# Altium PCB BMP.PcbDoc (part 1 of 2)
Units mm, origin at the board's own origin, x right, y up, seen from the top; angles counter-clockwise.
Board outline 171.87 x 76.56 mm, 2 copper layers (Top Layer, Bottom Layer); 88 components, 25 nets, 514 pads, 181 vias.
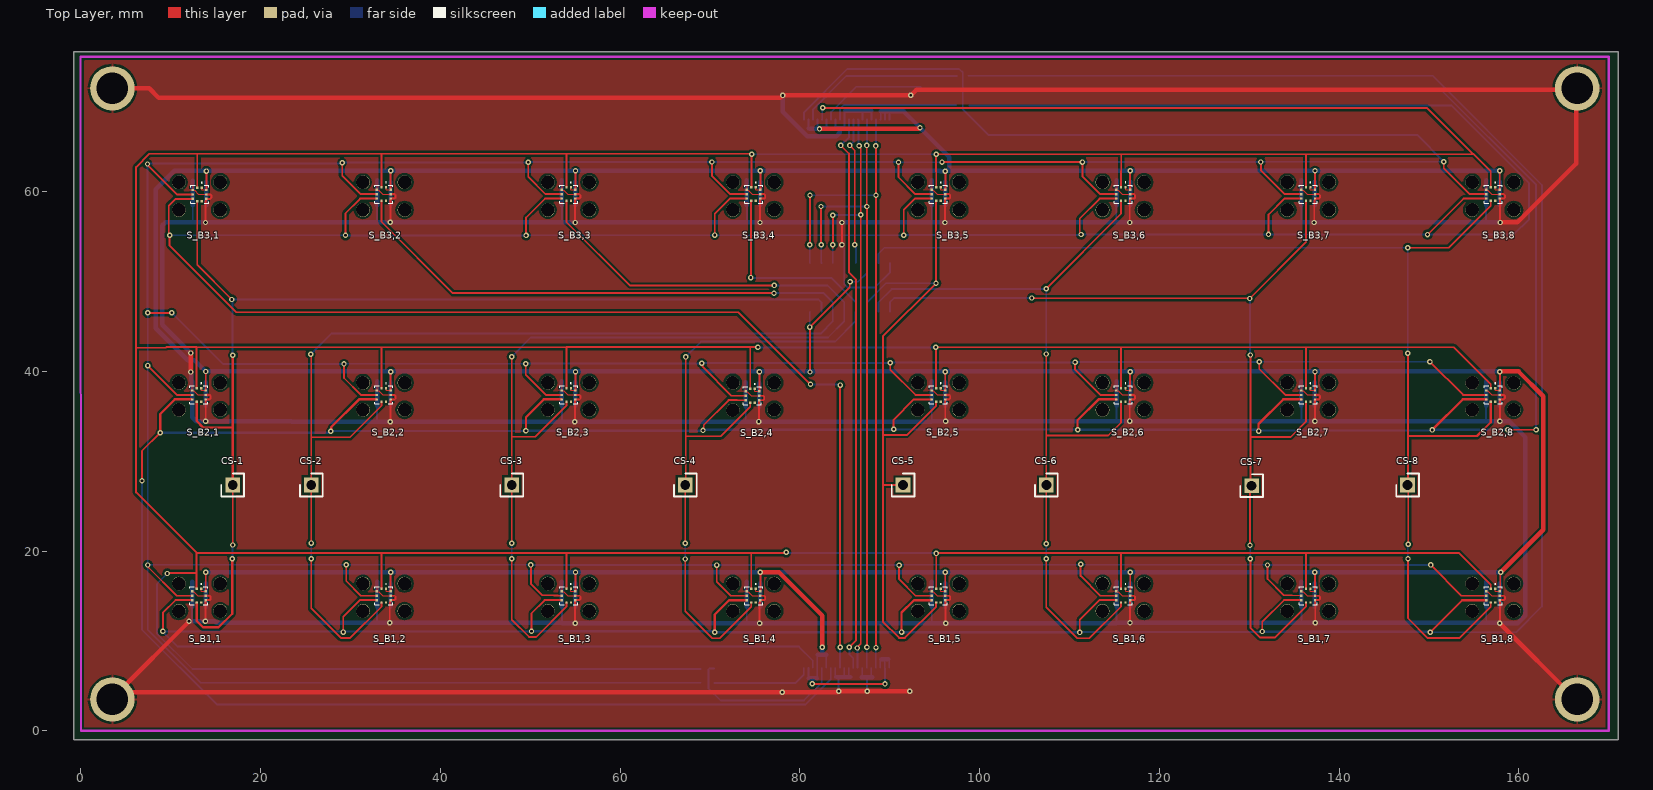
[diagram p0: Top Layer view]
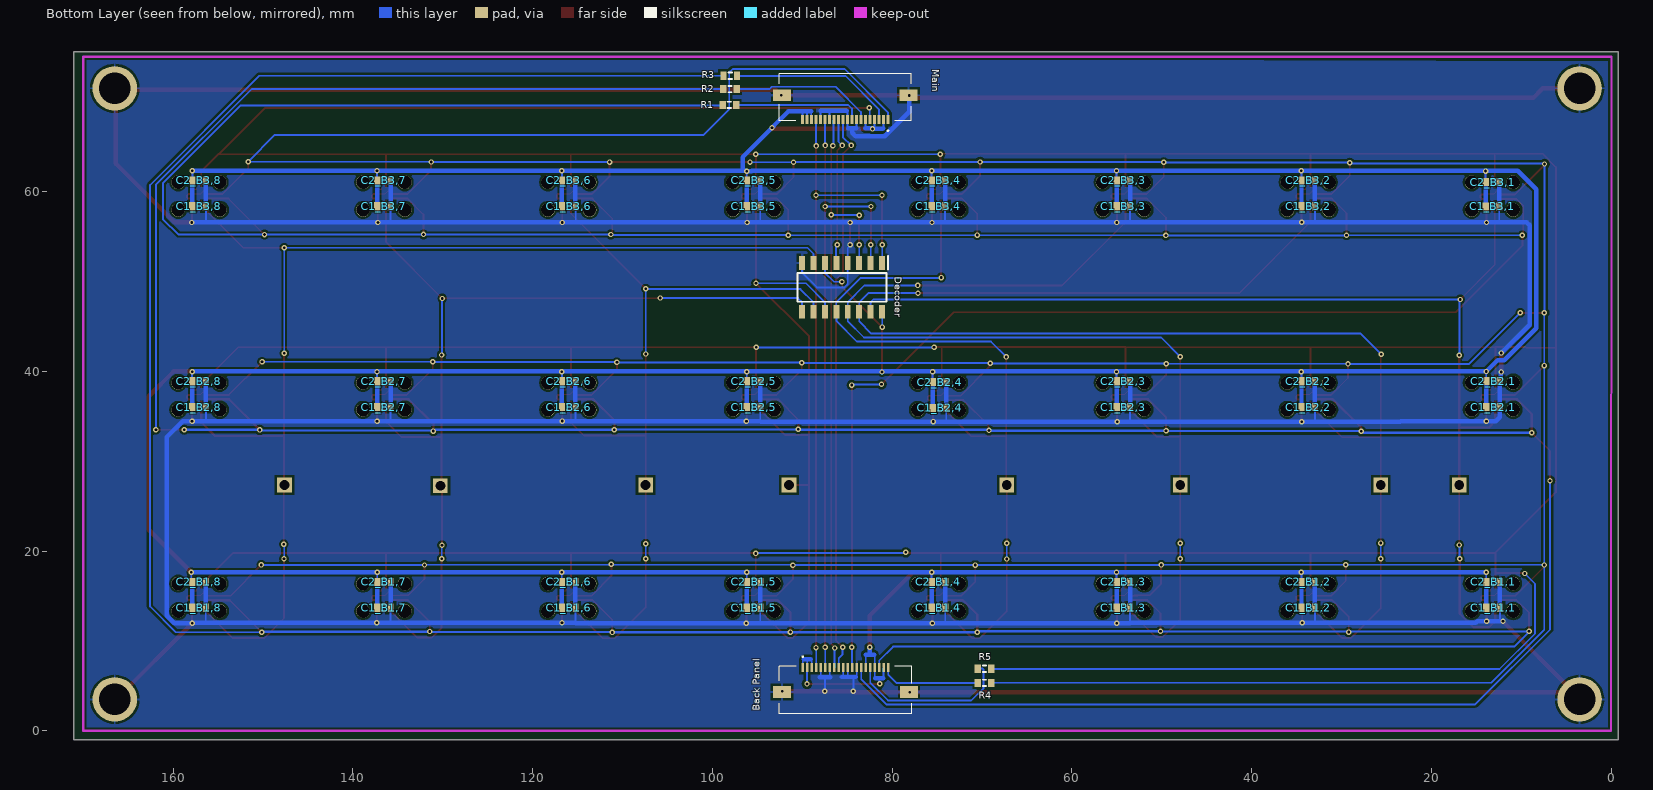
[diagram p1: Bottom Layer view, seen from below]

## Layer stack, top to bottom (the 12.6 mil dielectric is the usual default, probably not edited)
Top Solder: solder mask 0.0102, Solder Resist, Dk 3.5
Top Layer: signal copper 0.0356
Dielectric 1: dielectric 0.32, FR-4, Dk 4.8
Bottom Layer: signal copper 0.0356
Bottom Solder: solder mask 0.0102, Solder Resist, Dk 3.5

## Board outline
-0.805,-0.983 171.069,-0.983 171.069,75.573 -0.805,75.573

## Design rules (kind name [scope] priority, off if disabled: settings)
Clearance Clearance_1 [All] p1: gap=0.254 ignorepadtopadclearanceinfootprint=TRUE except(0: Arc-Hole Track-Hole SMDPad-Hole THPad-Hole Via-Hole Fill-Hole Poly-Hole Region-Hole Text-Hole; 0.2: Arc-SMDPad Track-SMDPad; 0.24: Arc-Arc Arc-Track Track-Track)
Clearance [All] p2: gap=0.254 ignorepadtopadclearanceinfootprint=TRUE except(0.5: Arc-THPad Arc-Hole Track-THPad Track-Hole)
ComponentClearance [All] p1: gap=0 collisioncheckmode=3 verticalgap=0.254 showdistances=FALSE
HoleSize HoleSize_1 [All] p1: absolutevalues=TRUE maxlimit=6 minlimit=0.025 maxpercent=80.000 minpercent=20.000
HoleSize [All] p2: absolutevalues=TRUE maxlimit=2.54 minlimit=0.025 maxpercent=80.000 minpercent=20.000
MinimumSolderMaskSliver MinimumSolderMaskSliver_PCB! [All] p1: minsoldermaskwidth=0
MinimumSolderMaskSliver [All] p2: minsoldermaskwidth=0.254
PolygonConnect pad [IsPad] p1: connectstyle=Relief reliefconductorwidth=0.254 reliefentries=4 polygonreliefangle="90 Angle" airgapwidth=0.254
PolygonConnect via [All] p2: connectstyle=Direct reliefconductorwidth=0.254 reliefentries=4 polygonreliefangle="90 Angle" airgapwidth=0.254
PolygonConnect [All] p3: connectstyle=Relief reliefconductorwidth=0.254 reliefentries=4 polygonreliefangle="90 Angle" airgapwidth=0.254
RoomDefinition B3,5 [InComponentClass('B3,5')] p1: confinementstyle=ConfineIn formatcopy=TRUE lockcomponents=FALSE outline 88.701,55.408 101.274,55.408 101.274,63.841 88.701,63.841
RoomDefinition B1,1 [InComponentClass('B1,1')] p2: confinementstyle=ConfineIn formatcopy=TRUE lockcomponents=FALSE outline 6.409,10.727 18.982,10.727 18.982,19.16 6.409,19.16
RoomDefinition B1,2 [InComponentClass('B1,2')] p3: confinementstyle=ConfineIn formatcopy=TRUE lockcomponents=FALSE outline 26.982,10.727 39.555,10.727 39.555,19.16 26.982,19.16
RoomDefinition B1,3 [InComponentClass('B1,3')] p4: confinementstyle=ConfineIn formatcopy=TRUE lockcomponents=FALSE outline 47.555,10.727 60.128,10.727 60.128,19.16 47.555,19.16
RoomDefinition B1,4 [InComponentClass('B1,4')] p5: confinementstyle=ConfineIn formatcopy=TRUE lockcomponents=FALSE outline 68.128,10.727 80.701,10.727 80.701,19.16 68.128,19.16
RoomDefinition B1,5 [InComponentClass('B1,5')] p6: confinementstyle=ConfineIn formatcopy=TRUE lockcomponents=FALSE outline 88.701,10.727 101.274,10.727 101.274,19.16 88.701,19.16
RoomDefinition B1,6 [InComponentClass('B1,6')] p7: confinementstyle=ConfineIn formatcopy=TRUE lockcomponents=FALSE outline 109.274,10.727 121.847,10.727 121.847,19.16 109.274,19.16
RoomDefinition B1,7 [InComponentClass('B1,7')] p8: confinementstyle=ConfineIn formatcopy=TRUE lockcomponents=FALSE outline 129.847,10.727 142.42,10.727 142.42,19.16 129.847,19.16
RoomDefinition B1,8 [InComponentClass('B1,8')] p9: confinementstyle=ConfineIn formatcopy=TRUE lockcomponents=FALSE outline 150.42,10.727 162.993,10.727 162.993,19.16 150.42,19.16
RoomDefinition B2,1 [InComponentClass('B2,1')] p10: confinementstyle=ConfineIn formatcopy=TRUE lockcomponents=FALSE outline 6.409,33.067 18.982,33.067 18.982,41.5 6.409,41.5
RoomDefinition B2,2 [InComponentClass('B2,2')] p11: confinementstyle=ConfineIn formatcopy=TRUE lockcomponents=FALSE outline 26.982,33.067 39.555,33.067 39.555,41.5 26.982,41.5
RoomDefinition B2,3 [InComponentClass('B2,3')] p12: confinementstyle=ConfineIn formatcopy=TRUE lockcomponents=FALSE outline 47.555,33.067 60.128,33.067 60.128,41.5 47.555,41.5
RoomDefinition B2,4 [InComponentClass('B2,4')] p13: confinementstyle=ConfineIn formatcopy=TRUE lockcomponents=FALSE outline 68.004,32.979 80.577,32.979 80.577,41.412 68.004,41.412
RoomDefinition B2,5 [InComponentClass('B2,5')] p14: confinementstyle=ConfineIn formatcopy=TRUE lockcomponents=FALSE outline 88.701,33.067 101.274,33.067 101.274,41.5 88.701,41.5
RoomDefinition B2,6 [InComponentClass('B2,6')] p15: confinementstyle=ConfineIn formatcopy=TRUE lockcomponents=FALSE outline 109.274,33.067 121.847,33.067 121.847,41.5 109.274,41.5
RoomDefinition B2,7 [InComponentClass('B2,7')] p16: confinementstyle=ConfineIn formatcopy=TRUE lockcomponents=FALSE outline 129.847,33.067 142.42,33.067 142.42,41.5 129.847,41.5
RoomDefinition B3,3 [InComponentClass('B3,3')] p17: confinementstyle=ConfineIn formatcopy=TRUE lockcomponents=FALSE outline 47.555,55.408 60.128,55.408 60.128,63.841 47.555,63.841
RoomDefinition B3,4 [InComponentClass('B3,4')] p18: confinementstyle=ConfineIn formatcopy=TRUE lockcomponents=FALSE outline 68.128,55.408 80.701,55.408 80.701,63.841 68.128,63.841
RoomDefinition B3,6 [InComponentClass('B3,6')] p19: confinementstyle=ConfineIn formatcopy=TRUE lockcomponents=FALSE outline 109.274,55.408 121.847,55.408 121.847,63.841 109.274,63.841
RoomDefinition B3,7 [InComponentClass('B3,7')] p20: confinementstyle=ConfineIn formatcopy=TRUE lockcomponents=FALSE outline 129.847,55.408 142.42,55.408 142.42,63.841 129.847,63.841
RoomDefinition B3,8 [InComponentClass('B3,8')] p21: confinementstyle=ConfineIn formatcopy=TRUE lockcomponents=FALSE outline 150.42,55.408 162.993,55.408 162.993,63.841 150.42,63.841
RoomDefinition B2,8 [InComponentClass('B2,8')] p22: confinementstyle=ConfineIn formatcopy=TRUE lockcomponents=FALSE outline 150.42,33.067 162.993,33.067 162.993,41.5 150.42,41.5
RoomDefinition B3,1 [InComponentClass('B3,1')] p23: confinementstyle=ConfineIn formatcopy=TRUE lockcomponents=FALSE outline 6.485,55.38 19.058,55.38 19.058,63.813 6.485,63.813
RoomDefinition B3,2 [InComponentClass('B3,2')] p24: confinementstyle=ConfineIn formatcopy=TRUE lockcomponents=FALSE outline 26.982,55.408 39.555,55.408 39.555,63.841 26.982,63.841
RoutingVias RoutingVias_1 [All] p1: holewidth=3.5 width=4 viastyle="Through Hole" minholewidth=0.3 minwidth=0.6 maxholewidth=6 maxwidth=6
RoutingVias [All] p2: holewidth=0.711 width=1.27 viastyle="Through Hole" minholewidth=0.711 minwidth=1.27 maxholewidth=0.711 maxwidth=1.27
SilkToSolderMaskClearance SilkToSolderMaskClearance_1 [IsPad] p1: minsilkscreentomaskgap=0 clearancetoexposedcopper=TRUE
SilkToSolderMaskClearance [IsPad] p2: minsilkscreentomaskgap=0.254 clearancetoexposedcopper=TRUE
SolderMaskExpansion [All] p1: expansion=0.102 istentingtop=FALSE
UnpouredPolygon UnpouredPolygon_1 [All] p1: allowunpoured=TRUE allowshelved=TRUE
UnpouredPolygon [All] p2:
Width POWER_GND [InNet('GND')] p1: maxlimit=0.508 minlimit=0.127 preferedwidth=0.5
Width POWER_+5V [InNet('+5')] p2: maxlimit=0.508 minlimit=0.2 preferedwidth=0.508
Width POWER_+3V3 [InNet('3V3')] p3: maxlimit=0.762 minlimit=0.127 preferedwidth=0.5
Width POWER_VDD [InNet('VDD')] p4: maxlimit=0.508 minlimit=0.2 preferedwidth=0.5
Width [All] p5: maxlimit=0.254 minlimit=0.2 preferedwidth=0.254
25 further rules are at their usual default settings.

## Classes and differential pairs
component class B3,8: C1_B3,8 C2_B3,8 S_B3,8
component class B3,7: C1_B3,7 C2_B3,7 S_B3,7
component class B3,6: C1_B3,6 C2_B3,6 S_B3,6
component class B3,5: C1_B3,5 C2_B3,5 S_B3,5
component class B3,4: C1_B3,4 C2_B3,4 S_B3,4
component class B3,3: C1_B3,3 C2_B3,3 S_B3,3
component class B3,2: C1_B3,2 C2_B3,2 S_B3,2
component class B3,1: C1_B3,1 C2_B3,1 S_B3,1
component class B2,8: C1_B2,8 C2_B2,8 S_B2,8
component class B2,7: C1_B2,7 C2_B2,7 S_B2,7
component class B2,6: C1_B2,6 C2_B2,6 S_B2,6
component class B2,5: C1_B2,5 C2_B2,5 S_B2,5
component class B2,4: C1_B2,4 C2_B2,4 S_B2,4
component class B2,3: C1_B2,3 C2_B2,3 S_B2,3
component class B2,2: C1_B2,2 C2_B2,2 S_B2,2
component class B2,1: C1_B2,1 C2_B2,1 S_B2,1
component class B1,8: C1_B1,8 C2_B1,8 S_B1,8
component class B1,7: C1_B1,7 C2_B1,7 S_B1,7
component class B1,6: C1_B1,6 C2_B1,6 S_B1,6
component class B1,5: C1_B1,5 C2_B1,5 S_B1,5
component class B1,4: C1_B1,4 C2_B1,4 S_B1,4
component class B1,3: C1_B1,3 C2_B1,3 S_B1,3
component class B1,2: C1_B1,2 C2_B1,2 S_B1,2
component class B1,1: C1_B1,1 C2_B1,1 S_B1,1
channel class BMP388: 1,1 1,2 1,3 1,4 1,5 1,6 1,7 1,8 2,1 2,2 2,3 2,4 2,5 2,6 2,7 2,8 3,1 3,2 3,3 3,4 3,5 3,6 3,7 3,8

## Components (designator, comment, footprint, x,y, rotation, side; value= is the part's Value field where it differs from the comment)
"Back Panel" "5051102091" 5051102091 85.19,4.556 r180 bottom
C1_B1,1 "Cap" J1-0603 13.121,13.699 r0 bottom value=100nF (schematic designator C1)
C1_B1,2 "Cap" J1-0603 33.694,13.699 r0 bottom value=100nF (schematic designator C1)
C1_B1,3 "Cap" J1-0603 54.267,13.699 r0 bottom value=100nF (schematic designator C1)
C1_B1,4 "Cap" J1-0603 74.84,13.699 r0 bottom value=100nF (schematic designator C1)
C1_B1,5 "Cap" J1-0603 95.413,13.699 r0 bottom value=100nF (schematic designator C1)
C1_B1,6 "Cap" J1-0603 115.986,13.699 r0 bottom value=100nF (schematic designator C1)
C1_B1,7 "Cap" J1-0603 136.559,13.699 r0 bottom value=100nF (schematic designator C1)
C1_B1,8 "Cap" J1-0603 157.132,13.699 r0 bottom value=100nF (schematic designator C1)
C1_B2,1 "Cap" J1-0603 13.121,36.039 r0 bottom value=100nF (schematic designator C1)
C1_B2,2 "Cap" J1-0603 33.694,36.039 r0 bottom value=100nF (schematic designator C1)
C1_B2,3 "Cap" J1-0603 54.267,36.039 r0 bottom value=100nF (schematic designator C1)
C1_B2,4 "Cap" J1-0603 74.716,35.951 r0 bottom value=100nF (schematic designator C1)
C1_B2,5 "Cap" J1-0603 95.413,36.039 r0 bottom value=100nF (schematic designator C1)
C1_B2,6 "Cap" J1-0603 115.986,36.039 r0 bottom value=100nF (schematic designator C1)
C1_B2,7 "Cap" J1-0603 136.559,36.039 r0 bottom value=100nF (schematic designator C1)
C1_B2,8 "Cap" J1-0603 157.132,36.039 r0 bottom value=100nF (schematic designator C1)
C1_B3,1 "Cap" J1-0603 13.198,58.352 r0 bottom value=100nF (schematic designator C1)
C1_B3,2 "Cap" J1-0603 33.694,58.38 r0 bottom value=100nF (schematic designator C1)
C1_B3,3 "Cap" J1-0603 54.267,58.38 r0 bottom value=100nF (schematic designator C1)
C1_B3,4 "Cap" J1-0603 74.84,58.38 r0 bottom value=100nF (schematic designator C1)
C1_B3,5 "Cap" J1-0603 95.413,58.38 r0 bottom value=100nF (schematic designator C1)
C1_B3,6 "Cap" J1-0603 115.986,58.38 r0 bottom value=100nF (schematic designator C1)
C1_B3,7 "Cap" J1-0603 136.559,58.38 r0 bottom value=100nF (schematic designator C1)
C1_B3,8 "Cap" J1-0603 157.132,58.38 r0 bottom value=100nF (schematic designator C1)
C2_B1,1 "Cap" J1-0603 13.122,16.566 r0 bottom value=100nF (schematic designator C2)
C2_B1,2 "Cap" J1-0603 33.695,16.566 r0 bottom value=100nF (schematic designator C2)
C2_B1,3 "Cap" J1-0603 54.267,16.566 r0 bottom value=100nF (schematic designator C2)
C2_B1,4 "Cap" J1-0603 74.84,16.566 r0 bottom value=100nF (schematic designator C2)
C2_B1,5 "Cap" J1-0603 95.414,16.566 r0 bottom value=100nF (schematic designator C2)
C2_B1,6 "Cap" J1-0603 115.986,16.566 r0 bottom value=100nF (schematic designator C2)
C2_B1,7 "Cap" J1-0603 136.559,16.566 r0 bottom value=100nF (schematic designator C2)
C2_B1,8 "Cap" J1-0603 157.132,16.566 r0 bottom value=100nF (schematic designator C2)
C2_B2,1 "Cap" J1-0603 13.128,38.921 r0 bottom value=100nF (schematic designator C2)
C2_B2,2 "Cap" J1-0603 33.695,38.907 r0 bottom value=100nF (schematic designator C2)
C2_B2,3 "Cap" J1-0603 54.267,38.907 r0 bottom value=100nF (schematic designator C2)
C2_B2,4 "Cap" J1-0603 74.716,38.819 r0 bottom value=100nF (schematic designator C2)
C2_B2,5 "Cap" J1-0603 95.414,38.907 r0 bottom value=100nF (schematic designator C2)
C2_B2,6 "Cap" J1-0603 115.986,38.907 r0 bottom value=100nF (schematic designator C2)
C2_B2,7 "Cap" J1-0603 136.559,38.907 r0 bottom value=100nF (schematic designator C2)
C2_B2,8 "Cap" J1-0603 157.132,38.907 r0 bottom value=100nF (schematic designator C2)
C2_B3,1 "Cap" J1-0603 13.179,61.07 r0 bottom value=100nF (schematic designator C2)
C2_B3,2 "Cap" J1-0603 33.695,61.247 r0 bottom value=100nF (schematic designator C2)
C2_B3,3 "Cap" J1-0603 54.267,61.247 r0 bottom value=100nF (schematic designator C2)
C2_B3,4 "Cap" J1-0603 74.84,61.247 r0 bottom value=100nF (schematic designator C2)
C2_B3,5 "Cap" J1-0603 95.414,61.247 r0 bottom value=100nF (schematic designator C2)
C2_B3,6 "Cap" J1-0603 115.986,61.247 r0 bottom value=100nF (schematic designator C2)
C2_B3,7 "Cap" J1-0603 136.559,61.247 r0 bottom value=100nF (schematic designator C2)
C2_B3,8 "Cap" J1-0603 157.132,61.247 r0 bottom value=100nF (schematic designator C2)
CS-1 "90120-0761" HDRV1W90P0X254_1X1_232X249X560P 16.886,27.356 r0 top
CS-2 "90120-0761" HDRV1W90P0X254_1X1_232X249X560P 25.628,27.356 r0 top
CS-3 "90120-0761" HDRV1W90P0X254_1X1_232X249X560P 47.938,27.356 r0 top
CS-4 "90120-0761" HDRV1W90P0X254_1X1_232X249X560P 67.246,27.356 r0 top
CS-5 "90120-0761" HDRV1W90P0X254_1X1_232X249X560P 91.491,27.356 r0 top
CS-6 "90120-0761" HDRV1W90P0X254_1X1_232X249X560P 107.425,27.356 r0 top
CS-7 "90120-0761" HDRV1W90P0X254_1X1_232X249X560P 130.277,27.28 r0 top
CS-8 "90120-0761" HDRV1W90P0X254_1X1_232X249X560P 147.627,27.356 r0 top
Decoder "SN74AHC138D" SOIC127P600X175-16N 85.573,49.352 r270 bottom
Main "5051102091" 5051102091 85.216,70.496 r0 bottom
R1 "Res1" J1-0603 98.108,69.647 r180 bottom value=100
R2 "Res1" J1-0603 98.044,71.425 r180 bottom value=100
R3 "Res1" J1-0603 98.019,72.898 r180 bottom value=100
R4 "Res1" J1-0603 69.723,5.334 r0 bottom value=100
R5 "Res1" J1-0603 69.723,6.909 r0 bottom value=100
S_B1,1 "BMP388" BMP388 13.122,15.046 r0 top (schematic designator S)
S_B1,2 "BMP388" BMP388 33.694,15.046 r0 top (schematic designator S)
S_B1,3 "BMP388" BMP388 54.267,15.046 r0 top (schematic designator S)
S_B1,4 "BMP388" BMP388 74.84,15.046 r0 top (schematic designator S)
S_B1,5 "BMP388" BMP388 95.413,15.046 r0 top (schematic designator S)
S_B1,6 "BMP388" BMP388 115.986,15.046 r0 top (schematic designator S)
S_B1,7 "BMP388" BMP388 136.559,15.046 r0 top (schematic designator S)
S_B1,8 "BMP388" BMP388 157.132,15.046 r0 top (schematic designator S)
S_B2,1 "BMP388" BMP388 13.122,37.387 r0 top (schematic designator S)
S_B2,2 "BMP388" BMP388 33.694,37.387 r0 top (schematic designator S)
S_B2,3 "BMP388" BMP388 54.267,37.387 r0 top (schematic designator S)
S_B2,4 "BMP388" BMP388 74.716,37.299 r0 top (schematic designator S)
S_B2,5 "BMP388" BMP388 95.413,37.387 r0 top (schematic designator S)
S_B2,6 "BMP388" BMP388 115.986,37.387 r0 top (schematic designator S)
S_B2,7 "BMP388" BMP388 136.559,37.387 r0 top (schematic designator S)
S_B2,8 "BMP388" BMP388 157.132,37.387 r0 top (schematic designator S)
S_B3,1 "BMP388" BMP388 13.198,59.7 r0 top (schematic designator S)
S_B3,2 "BMP388" BMP388 33.694,59.728 r0 top (schematic designator S)
S_B3,3 "BMP388" BMP388 54.267,59.728 r0 top (schematic designator S)
S_B3,4 "BMP388" BMP388 74.84,59.728 r0 top (schematic designator S)
S_B3,5 "BMP388" BMP388 95.413,59.728 r0 top (schematic designator S)
S_B3,6 "BMP388" BMP388 115.986,59.728 r0 top (schematic designator S)
S_B3,7 "BMP388" BMP388 136.559,59.728 r0 top (schematic designator S)
S_B3,8 "BMP388" BMP388 157.132,59.728 r0 top (schematic designator S)

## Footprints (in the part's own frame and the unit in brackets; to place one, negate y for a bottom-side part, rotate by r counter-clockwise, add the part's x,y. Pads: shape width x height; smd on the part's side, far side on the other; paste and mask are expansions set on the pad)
5051102091 [mm]
  rect 0.3x1 smd: 1(-4.75,2.475) 2(-4.25,2.475) 3(-3.75,2.475) 4(-3.25,2.475) 5(-2.75,2.475) 6(-2.25,2.475) 7(-1.75,2.475) 8(-1.25,2.475) 9(-0.75,2.475) 10(-0.25,2.475) 11(0.25,2.475) 12(0.75,2.475) 13(1.25,2.475) 14(1.75,2.475) 15(2.25,2.475) 16(2.75,2.475) 17(3.25,2.475) 18(3.75,2.475) 19(4.25,2.475) 20(4.75,2.475)
  rect 2x1.3 smd: MP1(-7.05,-0.225) MP2(7.05,-0.225)
  silkscreen extent -7.35,-2.63 7.35,3.75, body extent -7.75,-2.64 7.75,2.66, height 1.88
BMP388 [mm]
  rect 0.25x0.275 smd: 1(0.25,0.763) 2(-0.25,0.763) 6(-0.25,-0.763) 7(0.25,-0.763)
  rect 0.275x0.25 smd: 3(-0.762,0.5) 4(-0.762,0) 5(-0.762,-0.5) 8(0.762,-0.5) 9(0.762,0) 10(0.762,0.5)
  silkscreen extent -1,-1 1,1.35
HDRV1W90P0X254_1X1_232X249X560P [mm]
  rect 1.65x1.65 hole 1.1: 1(0,0)
  silkscreen extent -1.27,-1.27 1.27,1.27, body extent -1.27,-1.25 1.27,1.25, height 9.25
J1-0603 [mm] "Chip Resistor, Body 1.6x0.8mm, IPC High Density"
  rect 0.7x0.9 smd: 1(-0.75,0) 2(0.75,0)
  silkscreen extent -0.2,-0.35 0.2,0.35, body extent -0.85,-0.48 0.85,0.48, height 0.9
SOIC127P600X175-16N [mm]
  rect 1.525x0.65 smd: 1(-2.712,4.445) 2(-2.712,3.175) 3(-2.712,1.905) 4(-2.712,0.635) 5(-2.712,-0.635) 6(-2.712,-1.905) 7(-2.712,-3.175) 8(-2.712,-4.445) 9(2.712,-4.445) 10(2.712,-3.175) 11(2.712,-1.905) 12(2.712,-0.635) 13(2.712,0.635) 14(2.712,1.905) 15(2.712,3.175) 16(2.712,4.445)
  silkscreen extent -3.48,-4.95 1.6,5.12, body extent -3,-4.95 3,4.95, height 1.75

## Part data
"Back Panel" Main: "Connector", Manufacturer_Name=Molex
C1_B1,1 C1_B1,2 C1_B1,3 C1_B1,4 C1_B1,5 C1_B1,6 C1_B1,7 C1_B1,8 C1_B2,1 C1_B2,2 C1_B2,3 C1_B2,4 C1_B2,5 C1_B2,6 C1_B2,7 C1_B2,8 C1_B3,1 C1_B3,2 C1_B3,3 C1_B3,4 C1_B3,5 C1_B3,6 C1_B3,7 C1_B3,8 C2_B1,1 C2_B1,2 C2_B1,3 C2_B1,4 C2_B1,5 C2_B1,6 C2_B1,7 C2_B1,8 C2_B2,1 C2_B2,2 C2_B2,3 C2_B2,4 C2_B2,5 C2_B2,6 C2_B2,7 C2_B2,8 C2_B3,1 C2_B3,2 C2_B3,3 C2_B3,4 C2_B3,5 C2_B3,6 C2_B3,7 C2_B3,8: "Capacitor"
CS-1 CS-2 CS-3 CS-4 CS-5 CS-6 CS-7 CS-8: "Connector", Manufacturer_Name=Molex, Mouser Part Number=538-90120-0761
Decoder: "Integrated Circuit", Manufacturer_Name="Texas Instruments", Mouser Part Number=595-SN74AHC138D
R1 R2 R3 R4 R5: "Resistor"
S_B1,1 S_B1,2 S_B1,3 S_B1,4 S_B1,5 S_B1,6 S_B1,7 S_B1,8 S_B2,1 S_B2,2 S_B2,3 S_B2,4 S_B2,5 S_B2,6 S_B2,7 S_B2,8 S_B3,1 S_B3,2 S_B3,3 S_B3,4 S_B3,5 S_B3,6 S_B3,7 S_B3,8: "Pressure Sensor 4.35PSI ~ 18.13PSI _30kPa ~ 125kPa_ Absolute 10-WFLGA", Package="WFLGA-10 Bosch Tools"

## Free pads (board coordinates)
  round 4.95 hole 3.5 paste+0 mask+0.05: 1(3.5,3.5) 2(166.5,3.5) 3(166.5,71.5) 4(3.5,71.5)
  round 1.524 hole 1.5 paste+0 mask+0.102: 2(10.886,13.335) 2(10.886,35.72) 2(10.886,57.971) 2(31.383,13.335) 2(31.383,35.72) 2(31.383,57.971) 2(51.956,13.335) 2(51.956,35.72) 2(51.956,57.971) 2(72.529,13.335) 2(72.529,35.687) 2(72.529,57.971) 2(93.102,13.335) 2(93.102,35.72) 2(93.102,57.971) 2(113.675,13.335) 2(113.675,35.72) 2(113.675,57.971) 2(134.239,13.335) 2(134.239,35.72) 2(134.239,57.971) 2(154.821,13.335) 2(154.821,35.72) 2(154.821,57.971)
  round 1.524 hole 1.5 mask+0.102: 3(15.509,13.335) 3(15.509,35.72) 3(15.509,57.971) 3(36.006,13.335) 3(36.006,35.72) 3(36.006,57.971) 3(56.579,13.335) 3(56.579,35.72) 3(56.579,57.971) 3(77.152,13.335) 3(77.152,35.72) 3(77.152,57.971) 3(97.725,13.335) 3(97.725,35.72) 3(97.725,57.971) 3(118.298,13.335) 3(118.298,35.72) 3(118.298,57.971) 3(138.871,13.335) 3(138.871,35.72) 3(138.871,57.971) 3(159.444,13.335) 3(159.444,35.72) 3(159.444,57.971) 4(15.509,16.388) 4(15.509,38.729) 4(15.509,61.044) 4(36.006,16.388) 4(36.006,38.729) 4(36.006,61.044) 4(56.579,16.388) 4(56.579,38.729) 4(56.579,61.044) 4(77.152,16.388) 4(77.152,38.729) 4(77.152,61.044) 4(97.725,16.388) 4(97.725,38.729) 4(97.725,61.044) 4(118.298,16.388) 4(118.298,38.729) 4(118.298,61.044) 4(138.871,16.388) 4(138.871,38.729) 4(138.871,61.044) 4(159.444,16.388) 4(159.444,38.729) 4(159.444,61.044) 5(10.886,16.388) 5(10.886,38.729) 5(10.886,61.044) 5(31.383,16.388) 5(31.383,38.729) 5(31.383,61.044) 5(51.956,16.388) 5(51.956,38.729) 5(51.956,61.044) 5(72.529,16.388) 5(72.529,38.729) 5(72.529,61.044) 5(93.102,16.388) 5(93.102,38.729) 5(93.102,61.044) 5(113.675,16.388) 5(113.675,38.729) 5(113.675,61.044) 5(134.239,16.388) 5(134.239,38.729) 5(134.239,61.044) 5(154.821,16.388) 5(154.821,38.729) 5(154.821,61.044)

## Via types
v1: diameter 0.6, hole 0.3, Top Layer to Bottom Layer, tented both sides, 181 vias

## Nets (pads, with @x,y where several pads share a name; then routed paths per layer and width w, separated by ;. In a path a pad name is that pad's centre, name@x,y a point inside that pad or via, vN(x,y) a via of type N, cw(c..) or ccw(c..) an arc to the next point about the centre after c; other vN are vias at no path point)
3V3: "Back Panel.1" "Back Panel.2" "Back Panel.3" "Back Panel.15" "Back Panel.17" "Back Panel.19" C1_B1,1.2 C1_B1,2.2 C1_B1,3.2 C1_B1,4.2 C1_B1,5.2 C1_B1,6.2 C1_B1,7.2 C1_B1,8.2 C1_B2,1.2 C1_B2,2.2 C1_B2,3.2 C1_B2,4.2 C1_B2,5.2 C1_B2,6.2 C1_B2,7.2 C1_B2,8.2 C1_B3,1.2 C1_B3,2.2 C1_B3,3.2 C1_B3,4.2 C1_B3,5.2 C1_B3,6.2 C1_B3,7.2 C1_B3,8.2 C2_B1,1.2 C2_B1,2.2 C2_B1,3.2 C2_B1,4.2 C2_B1,5.2 C2_B1,6.2 C2_B1,7.2 C2_B1,8.2 C2_B2,1.2 C2_B2,2.2 C2_B2,3.2 C2_B2,4.2 C2_B2,5.2 C2_B2,6.2 C2_B2,7.2 C2_B2,8.2 C2_B3,1.2 C2_B3,2.2 C2_B3,3.2 C2_B3,4.2 C2_B3,5.2 C2_B3,6.2 C2_B3,7.2 C2_B3,8.2 Decoder.6 Decoder.16 Main.2 Main.4 Main.6 Main.18 Main.19 Main.20 S_B1,1.1 S_B1,1.10 S_B1,2.1 S_B1,2.10 S_B1,3.1 S_B1,3.10 S_B1,4.1 S_B1,4.10 S_B1,5.1 S_B1,5.10 S_B1,6.1 S_B1,6.10 S_B1,7.1 S_B1,7.10 S_B1,8.1 S_B1,8.10 S_B2,1.1 S_B2,1.10 S_B2,2.1 S_B2,2.10 S_B2,3.1 S_B2,3.10 S_B2,4.1 S_B2,4.10 S_B2,5.1 S_B2,5.10 S_B2,6.1 S_B2,6.10 S_B2,7.1 S_B2,7.10 S_B2,8.1 S_B2,8.10 S_B3,1.1 S_B3,1.10 S_B3,2.1 S_B3,2.10 S_B3,3.1 S_B3,3.10 S_B3,4.1 S_B3,4.10 S_B3,5.1 S_B3,5.10 S_B3,6.1 S_B3,6.10 S_B3,7.1 S_B3,7.10 S_B3,8.1 S_B3,8.10 | length 731.7
  Top Layer w0.127: 13.371,38.15 13.371,37.891 13.375,37.887 13.883,37.887 ; 13.416,15.765 13.371,15.809 13.371,15.55 13.375,15.546 13.883,15.546 ; 13.448,60.463 13.448,60.204 13.452,60.2 13.96,60.2 ; 33.944,38.15 33.944,37.891 33.948,37.887 34.456,37.887 ; 33.944,60.491 33.944,60.232 33.948,60.228 34.456,60.228 ; 33.989,15.765 33.944,15.809 33.944,15.55 33.948,15.546 34.456,15.546 ; 54.517,38.15 54.517,37.891 54.521,37.887 55.029,37.887 ; 54.517,60.491 54.517,60.232 54.521,60.228 55.029,60.228 ; 54.562,15.765 54.517,15.809 54.517,15.55 54.521,15.546 55.029,15.546 ; 74.966,38.062 74.966,37.803 74.97,37.799 75.478,37.799 ; 75.09,60.491 75.09,60.232 75.094,60.228 75.602,60.228 ; 75.135,15.765 75.09,15.809 75.09,15.55 75.094,15.546 75.602,15.546 ; 95.663,38.15 95.663,37.891 95.667,37.887 96.175,37.887 ; 95.663,60.491 95.663,60.232 95.667,60.228 96.175,60.228 ; 95.708,15.765 95.663,15.809 95.663,15.55 95.667,15.546 96.175,15.546 ; 116.236,38.15 116.236,37.891 116.24,37.887 116.748,37.887 ; 116.281,15.765 116.236,15.809 116.236,15.55 116.24,15.546 116.748,15.546 ; 116.281,60.446 116.236,60.491 116.236,60.232 116.24,60.228 116.748,60.228 ; 136.809,15.809 136.809,15.55 136.813,15.546 137.321,15.546 ; 136.809,38.15 136.809,37.891 136.813,37.887 137.321,37.887 ; 136.854,60.446 136.809,60.491 136.809,60.232 136.813,60.228 137.321,60.228 ; 157.382,15.809 157.382,15.55 157.386,15.546 157.894,15.546 ; 157.382,38.15 157.382,37.891 157.386,37.887 157.894,37.887 ; 157.382,60.491 157.382,60.232 157.386,60.228 157.894,60.228
  Top Layer w0.2: 13.883,15.546 v1(13.883,17.638) ; 13.883,37.887 13.888,37.892 13.888,39.974 v1@13.883,39.978 ; 13.96,60.2 v1(13.96,62.291) ; 34.456,15.546 v1(34.456,17.638) ; 34.456,37.887 v1(34.456,39.978) ; 34.456,60.228 v1(34.456,62.319) ; 55.029,15.546 v1(55.029,17.638) ; 55.029,37.887 v1(55.029,39.978) ; 55.029,60.228 v1(55.029,62.319) ; 75.478,37.799 75.497,37.817 v1(75.497,39.978) ; 75.602,15.546 v1(75.602,17.638) ; 75.602,60.228 v1(75.602,62.319) ; v1(81.126,39.93) 81.114,39.942 81.114,44.92 v1(81.102,44.933) 85.557,49.387 85.557,49.959 v1(85.585,49.987) ; v1(81.379,5.235) 81.384,5.23 89.47,5.23 v1(89.476,5.224) ; 96.175,15.546 v1(96.175,17.638) ; 96.175,37.887 v1(96.175,39.978) ; 96.175,60.228 96.19,60.242 v1(96.19,62.281) ; 116.748,15.546 116.768,15.566 v1(116.768,17.657) ; 116.748,37.887 v1(116.748,39.978) ; 116.748,60.228 v1(116.748,62.319) ; v1(137.305,17.654) 137.313,17.646 137.313,15.555 137.321,15.546 ; 137.321,37.887 v1(137.321,39.978) ; 137.321,60.228 v1(137.321,62.319) ; v1(157.869,62.319) 157.882,62.306 157.882,60.24 157.894,60.228 ; 157.894,15.546 157.907,15.546 157.932,15.571 157.932,17.597 v1(157.988,17.653) ; 157.894,37.887 v1(157.894,39.978)
  Top Layer w0.5: v1@13.883,39.978 v1(13.893,39.988) ; v1(75.602,17.638) 75.619,17.654 77.676,17.654 82.499,12.832 v1(82.499,9.296) ; v1(82.184,66.983) 93.222,66.983 93.338,67.099 v1(93.365,67.099) ; v1(157.894,39.978) 157.911,39.995 159.968,39.995 162.729,37.234 162.729,22.394 v1(157.988,17.653)
  Bottom Layer w0.2: 13.871,16.436 13.871,16.566 13.883,16.578 v1(13.883,17.638) ; 13.871,38.777 13.871,38.907 13.893,38.928 13.893,39.969 v1@13.883,39.978 ; 13.948,61.089 13.96,61.101 v1(13.96,62.291) ; 34.444,16.436 34.444,16.566 34.456,16.578 v1(34.456,17.638) ; 34.444,38.777 34.444,38.907 34.456,38.919 v1(34.456,39.978) ; 34.444,61.117 34.444,61.247 34.456,61.259 v1(34.456,62.319) ; 55.017,16.436 55.017,16.566 55.029,16.578 v1(55.029,17.638) ; 55.017,38.777 55.017,38.907 55.029,38.919 v1(55.029,39.978) ; 55.017,61.117 55.017,61.247 55.029,61.259 v1(55.029,62.319) ; 75.466,38.689 75.497,38.719 v1(75.497,39.978) ; 75.59,16.436 75.59,16.566 75.602,16.578 v1(75.602,17.638) ; 75.59,61.117 75.59,61.247 75.602,61.259 v1(75.602,62.319) ; 80.94,7.031 80.962,7.01 80.962,5.867 ; Main.2@80.966,68.021 80.975,68.012 80.975,67.056 ; v1(81.102,44.933) 81.102,46.615 Decoder.16@81.128,46.64 ; v1(81.379,5.235) 81.426,5.283 81.426,5.867 ; 81.85,5.867 81.94,5.957 81.94,8.435 81.997,8.492 ; v1@81.966,67.056 Main.4@81.966,68.021 ; 82.94,7.031 82.94,8.492 ; 82.966,67.056 Main.6@82.966,68.021 ; v1(85.585,49.987) 86.463,49.987 87.478,51.002 Decoder.6@87.478,52.064 ; 88.94,7.031 88.94,7.831 89.058,7.948 ; Main.18@88.966,68.021 89,68.055 89,68.96 ; 89.44,7.948 89.44,7.031 89.458,7.013 89.458,5.242 v1(89.476,5.224) ; 89.465,69.063 89.466,69.061 89.466,68.96 Main.19@89.466,68.021 ; 89.823,7.948 89.94,7.831 89.94,7.031 ; 89.964,68.96 89.964,68.023 Main.20@89.966,68.021 ; 96.163,16.436 96.163,16.566 96.175,16.578 v1(96.175,17.638) ; 96.163,38.777 96.163,38.907 96.175,38.919 v1(96.175,39.978) ; 96.164,61.247 96.183,61.267 96.183,62.288 v1@96.214,62.319 ; 116.736,16.436 116.768,16.468 v1(116.768,17.657) ; 116.736,38.777 116.736,38.907 116.748,38.919 v1(116.748,39.978) ; 116.736,61.117 116.736,61.247 116.748,61.259 v1(116.748,62.319) ; v1(137.305,17.654) 137.305,16.595 137.309,16.59 137.309,16.436 ; 137.309,38.777 137.309,38.907 137.321,38.919 v1(137.321,39.978) ; 137.309,61.117 137.309,61.247 137.321,61.259 v1(137.321,62.319) ; 157.882,16.436 157.882,16.566 157.988,16.672 v1(157.988,17.653) ; 157.882,38.777 157.882,38.907 157.894,38.919 v1(157.894,39.978) ; 157.882,61.247 157.869,61.261 157.869,62.268 v1@157.92,62.319
  Bottom Layer w0.5: 13.871,13.831 13.871,16.436 ; 13.871,36.172 13.875,36.175 13.875,38.774 13.871,38.777 ; v1@13.883,17.654 v1@55.029,17.654 ; 13.948,58.485 13.938,58.494 13.938,61.08 13.948,61.089 ; 34.444,13.831 34.444,16.436 ; 34.444,36.172 34.444,38.777 ; 34.444,58.513 34.444,61.117 ; 55.017,13.831 55.017,16.436 ; 55.017,36.172 55.017,38.777 ; 55.017,58.513 55.017,61.117 ; v1(55.029,17.638) 55.046,17.654 63.07,17.654 63.081,17.644 71.075,17.644 71.085,17.654 75.586,17.654 v1(75.602,17.638) ; 75.466,36.084 75.466,38.689 ; 75.59,13.831 75.59,16.436 ; 75.59,58.513 75.59,61.117 ; v1@75.641,17.657 83.501,17.657 83.52,17.638 91.372,17.638 91.391,17.657 v1@96.175,17.657 ; 80.962,5.867 81.426,5.867 81.85,5.867 ; 80.975,67.056 81.048,66.983 v1(82.184,66.983) ; v1@81.099,39.93 81.034,39.995 75.513,39.995 v1(75.497,39.978) 75.47,39.978 75.43,40.018 55.579,40.018 55.559,39.998 55.049,39.998 v1(55.029,39.978) 55.002,39.978 54.976,40.005 35.006,40.005 34.999,39.998 34.476,39.998 v1(34.456,39.978) 34.429,39.978 34.403,40.005 13.91,40.005 v1(13.893,39.988) 12.631,41.249 11.884,41.249 8.32,44.813 8.32,60.269 10.383,62.331 13.893,62.331 13.933,62.291 v1(13.96,62.291) 13.979,62.31 14.501,62.31 14.51,62.319 v1(34.456,62.319) v1(55.029,62.319) v1(75.602,62.319) 95.627,62.319 95.646,62.3 96.171,62.3 v1(96.19,62.281) ; v1(81.126,39.93) 81.153,39.93 81.242,40.018 96.108,40.018 96.148,39.978 v1(96.175,39.978) ; 81.997,8.492 82.469,8.492 ; v1@82.257,67.056 82.966,67.056 ; v1@82.453,9.296 82.48,9.269 82.48,8.503 82.469,8.492 ; 82.94,8.492 82.469,8.492 ; 89,68.96 89.466,68.96 89.964,68.96 91.539,68.96 v1@93.192,67.308 ; 89.058,7.948 89.44,7.948 89.823,7.948 ; v1@93.383,67.082 93.39,67.082 96.622,63.85 96.622,62.319 v1@96.214,62.319 ; 96.163,13.831 96.163,16.436 ; 96.163,36.172 96.163,38.777 ; 96.163,58.513 96.163,61.117 ; v1@96.175,39.995 116.748,39.995 137.321,39.995 v1@157.894,39.995 ; v1@96.195,17.657 v1(116.768,17.657) 124.59,17.657 124.594,17.653 132.37,17.653 132.372,17.654 v1(137.305,17.654) 157.987,17.654 v1(157.988,17.653) ; 96.628,62.313 116.742,62.313 v1(116.748,62.319) v1(137.321,62.319) v1(157.869,62.319) ; 116.736,13.831 116.736,16.436 ; 116.736,36.172 116.736,38.777 ; 116.736,58.513 116.736,61.117 ; 137.309,13.831 137.309,16.436 ; 137.309,36.172 137.309,38.777 ; 137.309,58.513 137.309,61.117 ; 157.882,13.831 157.882,16.436 ; 157.882,36.172 157.882,38.777 ; 157.882,58.513 157.882,61.117
CS-1: CS-1.1 Decoder.15 S_B1,1.6 S_B2,1.6 S_B3,1.6 | length 127.8
  Top Layer w0.2: 12.948,58.937 12.948,51.848 v1(16.789,48.006) ; v1(16.886,20.686) CS-1.1@16.886,27.356
  Top Layer w0.254: 12.872,14.283 12.872,12.217 13.569,11.519 15.31,11.519 16.829,13.039 v1(16.829,19.145) ; 12.872,36.624 12.872,34.476 13.586,33.761 16.901,33.761 ; CS-1.1@16.886,27.356 16.901,27.371 16.901,33.761 ; v1(16.901,41.801) 16.901,33.761
  Bottom Layer w0.2: 16.862,47.696 16.862,47.933 v1(16.789,48.006) 82.094,48.006 82.398,47.703 Decoder.15@82.398,46.64
  Bottom Layer w0.254: v1(16.829,19.145) 16.858,19.173 16.858,20.658 v1(16.886,20.686) ; 16.862,47.696 16.862,41.84 v1(16.901,41.801)
CS-2: CS-2.1 Decoder.14 S_B1,2.6 S_B2,2.6 S_B3,2.6 | length 167.1
  Top Layer w0.2: v1(25.56,41.918) 25.628,41.85 25.628,32.679 ; v1(25.628,19.146) 25.628,13.624 28.911,10.341 29.968,10.341 33.445,13.818 33.445,14.283 ; v1(25.628,20.896) 25.628,32.679 ; 33.445,36.624 33.445,36.187 29.937,32.679 25.628,32.679 ; 33.445,58.965 33.445,56.658 41.39,48.712 v1(77.122,48.712)
  Bottom Layer w0.2: v1(25.56,41.918) 27.852,44.21 82.3,44.21 83.668,45.578 83.668,47.703 82.658,48.712 v1(77.122,48.712) ; v1(25.628,19.146) v1(25.628,20.896)
CS-3: CS-3.1 Decoder.13 S_B1,3.6 S_B2,3.6 S_B3,3.6 | length 123.7
  Top Layer w0.2: v1(47.934,41.642) 47.934,32.73 ; v1(47.938,19.146) 47.938,12.372 49.865,10.445 50.644,10.445 54.018,13.818 54.018,14.283 ; v1(47.938,20.886) CS-3.1@47.938,27.356 47.934,27.359 47.934,32.73 ; 54.018,36.624 54.018,36.187 50.561,32.73 47.934,32.73 ; 54.018,58.965 54.018,56.623 61.075,49.566 v1(77.152,49.566)
  Bottom Layer w0.2: v1(47.934,41.642) 50.062,43.77 83.13,43.77 84.938,45.578 84.938,47.703 83.074,49.566 v1(77.152,49.566) ; v1(47.938,19.146) 47.938,20.855 v1@47.954,20.871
